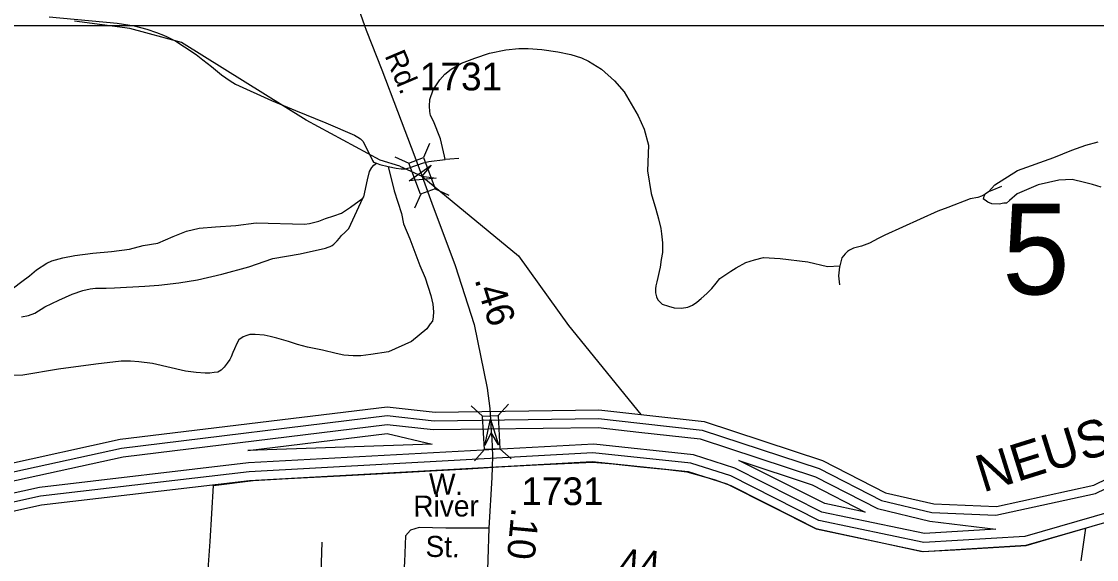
# Model space of a CAD drawing. Extents: x 2206922 to 2357709, y 510027 to 673830.
# Drawn here: x 2342384 to 2347243, y 539821 to 542251 of the extents above; entities that cross this region are included whole.
import ezdxf

# ---------------------------------------------------------------- set-up
doc = ezdxf.new("R2010")
doc.units = 0
for name, color, linetype in [('Exist Boundary Political City Limit New', 7, 'Continuous'), ('Exist Hydrographic Buffer Line', 7, 'Continuous'), ('Exist Hydrographic Creek Single Shore', 7, 'Continuous'), ('Exist Hydrographic Misc Water Feature', 7, 'Continuous'), ('Exist Hydrographic River Shore', 7, 'Continuous'), ('Exist Hydrographic River Shore Label', 7, 'Continuous'), ('Exist Road Non-System Type 51', 7, 'Continuous'), ('Exist Road Non-System Type 51 Label', 7, 'Continuous'), ('Exist Road Secondary Mileage Hundredths English Label', 7, 'Continuous'), ('Exist Road Secondary Structure Standard Bridge Attributed CELL', 7, 'Continuous'), ('Exist Road Secondary Structure Standard Bridge CELL', 7, 'Continuous'), ('Exist Road Secondary Structure Standard Bridge Number Label', 7, 'Continuous'), ('Exist Road Secondary Type 51 Attributed', 7, 'Continuous'), ('Exist Road Secondary Type 51 Label', 7, 'Continuous'), ('Exist Road Secondary Type 51 Number Label', 7, 'Continuous'), ('Map Preparation Boundary City Limit Buffer Line', 7, 'Continuous'), ('Map Preparation Inset Cut Line', 7, 'Continuous')]:
    doc.layers.add(name, color=color, linetype=linetype)

msp = doc.modelspace()

# ---------------------------------------------------------------- linework, layer by layer
at = {"layer": 'Exist Boundary Political City Limit New'}
msp.add_lwpolyline([(2343225.5, 539734.2), (2343236.5, 539902.8), (2343252.5, 540155.8), (2343431, 540177.4), (2343589, 540186.9), (2343824.2, 540199.1), (2344048, 540211.2), (2344235.8, 540222.1), (2344400.8, 540230.2), (2344540, 540239.6), (2344711.5, 540247.8), (2344967, 540259.9), (2345057.5, 540253.2), (2345181.8, 540239.6), (2345304.8, 540227.5), (2345391.2, 540216.7), (2345514.2, 540181.5), (2345590, 540154.4), (2345884.8, 540005.7), (2345973.8, 539961.1), (2346156.2, 539921.8), (2346281.2, 539894.8), (2346454.2, 539856.9), (2346603, 539865), (2346924, 539883.9), (2347042.8, 539919.1), (2347193, 539962.4), (2347171.2, 539815.2)], dxfattribs=at)
at = {"layer": 'Exist Hydrographic Buffer Line'}
for points in [[(2346788.3, 540020.9), (2347238.6, 540118.3), (2347636.6, 540311), (2347963.6, 540592.4), (2348361, 540798.5), (2348643.8, 540883.2), (2349059.6, 540899.9)], [(2336965.7, 540880.3), (2338111.1, 540591.4), (2338788.6, 540490.1), (2339287.7, 540382.7), (2339905.7, 540220.9), (2340959.9, 540032.9), (2341559.5, 540056.1), (2342306.1, 540208.1), (2342836.7, 540324.4), (2344036.3, 540470.7), (2344248.5, 540447.1), (2344992, 540457.1), (2345179.2, 540436.1), (2345460.6, 540404.8), (2345988.6, 540231.6), (2346270.7, 540087), (2346498.1, 540033.4), (2346788.3, 540020.9)], [(2348344.4, 540558.7), (2347655, 540165.6), (2347310.6, 540038.4), (2346918.3, 539925.4), (2346462, 539897.4), (2345988.4, 539997.1), (2345590, 540198.4), (2345409.1, 540256.1), (2344967, 540302.7), (2343412.7, 540217.4), (2342470.3, 540107.1), (2341432.7, 539878.5)], [(2342314, 540169), (2342843.5, 540284.9), (2344036.5, 540430.4), (2344244.2, 540407.4), (2344990, 540417), (2345174.7, 540396.4), (2345452, 540365.5), (2345973, 540194.6), (2346252.5, 540051.5), (2346489.1, 539994.4), (2346788.3, 539957.6), (2346465.1, 539937.6), (2346001.9, 540035.2), (2345608, 540234.1), (2345421, 540294.2), (2344971.3, 540342.4), (2343410.5, 540257.3), (2342465.8, 540146.8), (2341428.4, 539918.5)], [(2343406.6, 540313.3), (2344036.7, 540390.1), (2344240.9, 540342.4), (2343406.6, 540313.3)], [(2346197.3, 540034.9), (2346015, 540073.3), (2345625.6, 540268.3), (2345957.8, 540157.6), (2346197.3, 540034.9)]]:
    msp.add_lwpolyline(points, dxfattribs=at)
at = {"layer": 'Exist Hydrographic Creek Single Shore'}
for points in [[(2344094.8, 541598.1), (2344005.9, 541625.5), (2343670.1, 541805.6), (2343108, 542157.1), (2342874, 542219.8), (2342623.9, 542252.4)], [(2344094.8, 541598.1), (2344193.5, 541552.5), (2344629.9, 541193.2), (2344856.7, 540878), (2345183.8, 540475.9)]]:
    msp.add_lwpolyline(points, dxfattribs=at)
at = {"layer": 'Exist Hydrographic Misc Water Feature'}
for p, q in [((2346755.1, 541481.1), (2346739.5, 541470.8)), ((2346082.1, 541147.2), (2346081.7, 541143.2))]:
    msp.add_line(p, q, dxfattribs=at)
for points in [[(2342509.7, 542271.6), (2342816.2, 542243.3), (2342894.1, 542232.4), (2342950.3, 542217.1), (2342994.4, 542201.5), (2343026.6, 542189.8), (2343042.6, 542182.1), (2343081.1, 542162.5), (2343121.5, 542137), (2343173.4, 542101.6), (2343203.8, 542077.9), (2343242.3, 542048.7), (2343288.3, 542010.9), (2343327.2, 541983.6), (2343350.8, 541967.9), (2343514, 541893.9), (2343622.3, 541849.2), (2343759.1, 541792.9), (2343889.5, 541738.4), (2343904, 541728.6), (2343915.9, 541720.7), (2343926.2, 541711.1), (2343956.5, 541651.3), (2343971.1, 541623.6), (2343975, 541615.7), (2343989.1, 541611.6)], [(2344298.5, 541627.4), (2344296.5, 541643.5), (2344277.6, 541721), (2344246.7, 541800.7), (2344232.3, 541826.8), (2344230.1, 541844.5), (2344227.8, 541868.4), (2344229.4, 541898.6), (2344245.2, 541942.5), (2344274.8, 541987.1), (2344297.7, 542013.2), (2344325.8, 542035.8), (2344373.4, 542062.3), (2344433.3, 542084.9), (2344498.7, 542107.5), (2344572.7, 542122.7), (2344632.4, 542129.2), (2344674.6, 542129.7), (2344736.5, 542124.4), (2344808.7, 542113.6), (2344866.7, 542102), (2344914.7, 542086.7), (2344947.1, 542071.3), (2345005.8, 542035.7), (2345064, 541982.7), (2345108.5, 541933), (2345171.9, 541825.8), (2345198.5, 541764.2), (2345217.6, 541692.4), (2345213.3, 541576.7), (2345230.3, 541474.8), (2345251.2, 541403.1), (2345263.3, 541359.1), (2345274, 541315.4), (2345276.4, 541291.5), (2345280.7, 541251.4), (2345281.6, 541207.5), (2345275.8, 541175.6), (2345270.1, 541141.5), (2345266.4, 541121.4), (2345260.6, 541095.5), (2345255.3, 541075.2), (2345251.4, 541057.2), (2345249.6, 541043.3), (2345249.4, 541025), (2345253.7, 541007.4), (2345259.8, 540993.4), (2345280.3, 540973.7), (2345308, 540965.9), (2345334.5, 540958.3), (2345366.5, 540956.7), (2345396.4, 540961.1), (2345416.1, 540969.1), (2345436, 540983.6), (2345456.1, 540999.6), (2345481.5, 541022.2), (2345503.4, 541044.4), (2345523.1, 541068.6), (2345540.5, 541090.7), (2345558.6, 541103), (2345590.6, 541123.4), (2345614.2, 541137.7), (2345657.6, 541161.9), (2345697.6, 541174.6), (2345737.2, 541185.2), (2345813.3, 541179.9), (2345937.5, 541165.3), (2346027.5, 541144.4), (2346082.1, 541147.2)], [(2346755.1, 541481.1), (2346783, 541513.4), (2346886.1, 541578.5), (2347049.1, 541636.8), (2347130.7, 541669.5), (2347194.5, 541692.3), (2347250.5, 541707.1)], [(2343927, 541453), (2343931.1, 541459.3), (2343948.3, 541535.4), (2343957.5, 541573.3), (2343967, 541591.4), (2343977.2, 541601.6), (2343989.1, 541611.6)], [(2343989.1, 541611.6), (2344003.5, 541605.8), (2344041.4, 541596.4)], [(2344041.4, 541596.4), (2344077.1, 541589), (2344099.4, 541585.2), (2344119.5, 541585.5), (2344135.5, 541589.6), (2344200.7, 541612.2), (2344224.9, 541618.7), (2344298.5, 541627.4)], [(2344360.7, 541632.3), (2344320.7, 541629.8), (2344298.5, 541627.4)], [(2344041.4, 541596.4), (2344068.7, 541486.9), (2344101.5, 541383.4), (2344110.5, 541337.4), (2344139.2, 541269.8), (2344184.3, 541148.3), (2344209.1, 541092.7), (2344234.2, 541013.1), (2344242.8, 540974.9), (2344246.9, 540939), (2344245.4, 540917.3), (2344241.7, 540897.2), (2344231.5, 540884.9), (2344215.9, 540862.9), (2344147, 540806), (2344043, 540758.7), (2343963.5, 540747.6), (2343917.4, 540741.2), (2343883.7, 540741), (2343841.5, 540744.5), (2343805.6, 540751.9), (2343745.3, 540767), (2343677.4, 540780.5), (2343631.3, 540791.9), (2343590.9, 540805.3), (2343538.6, 540820.8), (2343508.5, 540828.2), (2343481, 540834), (2343440.8, 540837.6), (2343416.8, 540837.1), (2343402.7, 540833.2), (2343386.7, 540827.1), (2343367, 540812.6), (2343357.4, 540796.6), (2343347.5, 540772.5), (2343339.7, 540756.3), (2343332.1, 540736.3), (2343325.8, 540724.3), (2343314.3, 540707.8), (2343300.6, 540690), (2343286.8, 540675.8), (2343271, 540667.7), (2343254.8, 540665.2), (2343234.9, 540663), (2343214.8, 540662.7), (2343173, 540666.2), (2343125, 540671.8), (2342976.4, 540705.9), (2342914.2, 540713.2), (2342876.7, 540716.9), (2342834.5, 540716.3), (2342720.9, 540703), (2342551.1, 540681.1), (2342389.5, 540653), (2342301.5, 540650.1)], [(2347263, 541503.2), (2347224.8, 541514.7), (2347188.5, 541524.1), (2347132.6, 541537.4), (2347072.7, 541534.7), (2346978.6, 541513.9), (2346883.4, 541472.7), (2346849.8, 541442.1), (2346835.9, 541430), (2346824, 541430.1), (2346802, 541425.8), (2346770, 541427.3), (2346752.2, 541435.3), (2346739.7, 541444.8), (2346731.9, 541448.8), (2346735.6, 541462.9), (2346739.5, 541470.8)], [(2346739.5, 541470.8), (2346723.5, 541462.7), (2346706.1, 541456.4), (2346671.8, 541450.2), (2346570.3, 541410.7), (2346524.8, 541394.5), (2346286.1, 541285.6), (2346256, 541271.1), (2346216.6, 541250.6), (2346180.5, 541236.2), (2346144.6, 541227.8), (2346126.8, 541217.5), (2346116.9, 541211.6), (2346107.1, 541201.4), (2346091.3, 541183.1), (2346082.1, 541147.2)], [(2346813.3, 541506), (2346769.4, 541487.4), (2346755.1, 541481.1)], [(2342348.7, 541048.5), (2342386.2, 541076.9), (2342420.3, 541103), (2342451.8, 541129.5), (2342499, 541160.1), (2342521.2, 541170.1), (2342570.8, 541182.9), (2342624.9, 541193.5), (2342706.7, 541204.7), (2342790.6, 541211.5), (2342872.4, 541222.3), (2342933.9, 541239.4), (2342999.7, 541250.2), (2343069.5, 541280.7), (2343129.3, 541303.7), (2343187.2, 541318.1), (2343261, 541323.2), (2343352.6, 541330.1), (2343444.7, 541341.4), (2343662.7, 541335.8), (2343686.5, 541338.3), (2343728.1, 541348.7), (2343758.2, 541361.2), (2343796, 541373.4), (2343830, 541386.1), (2343871.4, 541412.3), (2343927, 541453)], [(2342384.2, 540916.6), (2342416.2, 540923.1), (2342443.8, 540933.6), (2342489.8, 540961.9), (2342553.1, 540992.6), (2342613, 541019.7), (2342660.8, 541036), (2342694.4, 541044.3), (2342718.6, 541046.7), (2342766.2, 541047.3), (2342804.5, 541047.6), (2342942.3, 541055.3), (2343004.3, 541060.2), (2343095.9, 541071.1), (2343179.6, 541084.5), (2343289.7, 541109.7), (2343411.3, 541142.9), (2343520.8, 541180.4), (2343644.2, 541202), (2343757.6, 541227.1), (2343769.7, 541231.3), (2343779.8, 541235.5), (2343787.8, 541239.6), (2343795.6, 541245.7), (2343801.7, 541251.7), (2343811.5, 541259.9), (2343821.2, 541271.8), (2343830.8, 541284.2), (2343845.2, 541298.2), (2343863, 541316.2), (2343927, 541453)], [(2346081.7, 541143.2), (2346076.3, 541103), (2346080.9, 541061.4)]]:
    msp.add_lwpolyline(points, dxfattribs=at)
at = {"layer": 'Exist Hydrographic River Shore'}
for points in [[(2336021.4, 541405.3), (2336238.8, 541266.4), (2336665.9, 541080.2), (2336983.9, 540915.8), (2338120.9, 540630.2), (2338796, 540529.4), (2339296.9, 540421.7), (2339916, 540259.5), (2340967.1, 540072.2), (2341558, 540096.1), (2342298.1, 540247.3), (2342830, 540363.9), (2344036.1, 540510.9), (2344253, 540486.9), (2344994.1, 540497), (2345183.8, 540475.9)], [(2345183.8, 540475.9), (2345469, 540444.1), (2346004, 540268.7), (2346289, 540122.7), (2346507.2, 540072.4), (2346790.1, 540060.8), (2347230.2, 540157.3), (2347619.2, 540346.9), (2347941.1, 540625.8), (2348346.1, 540835.7), (2348637, 540922.9), (2349061.1, 540940)], [(2338557.9, 540277), (2338975, 540215), (2340944.9, 539841.6), (2341437, 539838.4), (2342475, 540067.4), (2343415, 540177.4), (2344963.1, 540262.9), (2345397, 540218), (2345572.1, 540162.7), (2345975, 539959), (2346459, 539857.1), (2346925.1, 539885.8), (2347323.1, 540000.3), (2347672.1, 540129.2), (2348358.2, 540521.1), (2348640.1, 540624.4), (2349049, 540620.3)]]:
    msp.add_lwpolyline(points, dxfattribs=at)
at = {"layer": 'Exist Road Non-System Type 51'}
msp.add_line((2343741.7, 539899.9), (2343735.6, 539712.7), dxfattribs=at)
msp.add_lwpolyline([(2344496.6, 539962.9), (2344302.7, 539962.5), (2344180.8, 539965), (2344142.9, 539952.7), (2344119.2, 539928.3), (2344114.6, 539810.3), (2344107.8, 539700.2)], dxfattribs=at)
at = {"layer": 'Exist Road Secondary Structure Standard Bridge Attributed CELL'}
for points in [[(2344257.8, 541543.1), (2344136.4, 541531), (2344235.5, 541602.1), (2344193.5, 541552.5)], [(2344477.6, 540335.7), (2344504.1, 540454.8), (2344540.7, 540338.5), (2344506.7, 540393.9)]]:
    msp.add_lwpolyline(points, close=True, dxfattribs=at)
at = {"layer": 'Exist Road Secondary Structure Standard Bridge CELL'}
for p, q in [((2344228.7, 541699.6), (2344200.3, 541636.8)), ((2344071.3, 541640.3), (2344134.2, 541611.8)), ((2344188.8, 541470.9), (2344160.3, 541408)), ((2344253.3, 541495.3), (2344316.2, 541466.9)), ((2344417.1, 540514.6), (2344468.3, 540468.4)), ((2344585, 540523.2), (2344538.8, 540472)), ((2344477.3, 540317.5), (2344431.1, 540266.3)), ((2344546.2, 540321.1), (2344597.4, 540274.9))]:
    msp.add_line(p, q, dxfattribs=at)
for points in [[(2344200.3, 541636.8), (2344253.6, 541495.4), (2344187.6, 541470.5), (2344134.2, 541611.8)], [(2344538.8, 540472), (2344546.5, 540321.1), (2344476, 540317.5), (2344468.3, 540468.4)]]:
    msp.add_lwpolyline(points, close=True, dxfattribs=at)
at = {"layer": 'Exist Road Secondary Type 51 Attributed'}
for points in [[(2343818.6, 542561.7), (2343840.2, 542498.4), (2343889.1, 542363.2), (2343935, 542232.7), (2343942.2, 542212.2), (2344012.8, 542032.5), (2344083.2, 541845.6), (2344162.5, 541640.2), (2344201.4, 541534.3)], [(2344201.4, 541534.3), (2344239.2, 541431.2), (2344344.8, 541149.5), (2344430, 540882.8), (2344489.5, 540594.9), (2344501.4, 540503.6), (2344507.3, 540402.4), (2344509.2, 540367.8)], [(2344509.2, 540367.8), (2344513.3, 540289.3), (2344511.2, 540237.7), (2344509.3, 540192), (2344496.6, 539962.9), (2344487.5, 539678.9)]]:
    msp.add_lwpolyline(points, dxfattribs=at)
at = {"layer": 'Map Preparation Boundary City Limit Buffer Line'}
msp.add_lwpolyline([(2343225.5, 539734.2), (2343236.5, 539902.8), (2343252.5, 540155.8), (2343431, 540177.4), (2343589, 540186.9), (2343824.2, 540199.1), (2344048, 540211.2), (2344235.8, 540222.1), (2344400.8, 540230.2), (2344540, 540239.6), (2344711.5, 540247.8), (2344967, 540259.9), (2345057.5, 540253.2), (2345181.8, 540239.6), (2345304.8, 540227.5), (2345391.2, 540216.7), (2345514.2, 540181.5), (2345590, 540154.4), (2345884.8, 540005.7), (2345973.8, 539961.1), (2346156.2, 539921.8), (2346281.2, 539894.8), (2346454.2, 539856.9), (2346603, 539865), (2346924, 539883.9), (2347042.8, 539919.1), (2347193, 539962.4), (2347171.2, 539815.2)], dxfattribs=at)
at = {"layer": 'Map Preparation Inset Cut Line'}
msp.add_line((2343935, 542232.7), (2347708, 542232.7), dxfattribs=at)
msp.add_lwpolyline([(2340379.2, 536458.2), (2340379.2, 542232.7), (2343935, 542232.7)], dxfattribs=at)

# ---------------------------------------------------------------- texts
at = {"layer": 'Exist Hydrographic River Shore Label'}
msp.add_text('NEUSE', height=167.32, rotation=17.3603, dxfattribs=at).set_placement((2346729.7, 540122.8))
at = {"layer": 'Exist Road Non-System Type 51 Label'}
for s, rotation, p in [('W.', 358.8251, (2344223.9, 540115.6)), ('River', 0.1183, (2344154.7, 540014.7)), ('St.', 358.8251, (2344209.3, 539833.3))]:
    msp.add_text(s, height=95, rotation=rotation, dxfattribs=at).set_placement(p)
at = {"layer": 'Exist Road Secondary Mileage Hundredths English Label'}
for s, rotation, p in [('.46', 287.7087, (2344430.7, 541085.9)), ('.10', 264.6614, (2344599.9, 540058.1)), ('.44', 356.2522, (2345035.7, 539748.6))]:
    msp.add_text(s, height=125, rotation=rotation, dxfattribs=at).set_placement(p)
at = {"layer": 'Exist Road Secondary Structure Standard Bridge Number Label'}
msp.add_text('5', height=410.1, dxfattribs=at).set_placement((2346816.4, 541018.5))
at = {"layer": 'Exist Road Secondary Type 51 Label'}
msp.add_text('Rd.', height=95, rotation=293.0321, dxfattribs=at).set_placement((2344024.1, 542097))
at = {"layer": 'Exist Road Secondary Type 51 Number Label'}
for p in [(2344184.7, 541940.1), (2344643.2, 540066.7)]:
    msp.add_text('1731', height=125, dxfattribs=at).set_placement(p)

doc.saveas('drawing.dxf')
